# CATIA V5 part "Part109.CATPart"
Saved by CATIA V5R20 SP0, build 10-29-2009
Part number: FA 063200-3
Revision: ANY
Definition: UNKNOWN
Nomenclature: FA 063200-3
Source: Unknown
Bounding box of the stored display mesh (mm): x -2.109 to 2.109, y -2.45 to 2.45, z -2 to 2
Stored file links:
  C:\Users\Utente\Desktop\IO LAVORO\3D X SITO CF\CUMSA\3D files FA\FA 063212-20\Part109.CATPart

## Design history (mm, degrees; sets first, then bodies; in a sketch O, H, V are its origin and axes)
Body1 "Chaflán4" (main body)
  Solid1: solid without history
